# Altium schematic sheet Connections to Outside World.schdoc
size 78 x 103 mm
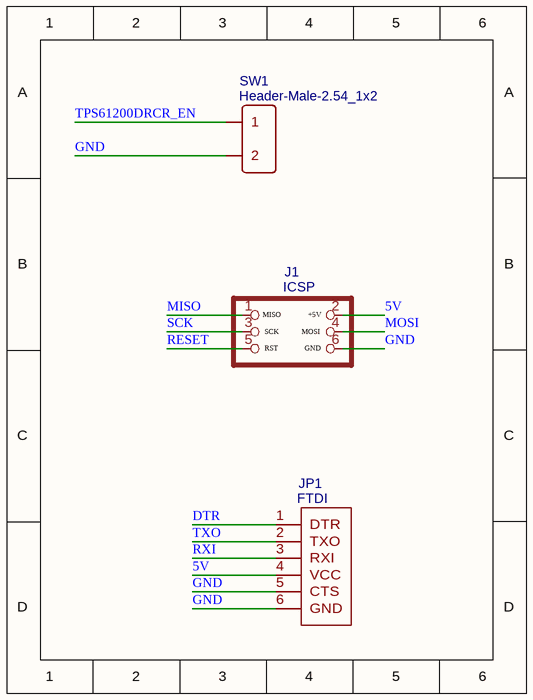
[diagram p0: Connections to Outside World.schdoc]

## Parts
J1  ICSP  [HEADER_PRG_2X03]
JP1  FTDI  [FTDI]
SW1  Header-Male-2.54_1x2  [HDR-2X1/2.54]

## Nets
5V: J1.2(+V) JP1.4(VCC)
DTR: JP1.1(DTR)
GND: J1.6(GND) JP1.5(CTS) JP1.6(GND) SW1.2
MISO: J1.1(MISO)
MOSI: J1.4(MOSI)
RESET: J1.5(RST)
RXI: JP1.3(RXI)
SCK: J1.3(SCK)
TPS61200DRCR_EN: SW1.1
TXO: JP1.2(TXO)

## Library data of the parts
J1 = ICSP: Contributor: Gareth Burrows
JP1 = FTDI: Contributor: fukssvans
SW1 = Header-Male-2.54_1x2: BOM_Manufacturer: TE Connectivity; BOM_Manufacturer Part: 826629-2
